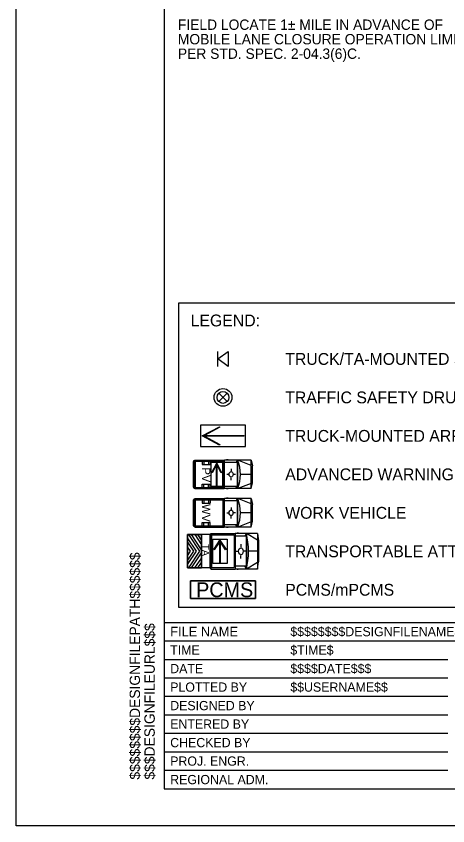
# Model space of a CAD drawing. Extents: x 0 to 17, y 0 to 11.
# Drawn here: x 0 to 2.92, y 0 to 5.47 of the extents above; entities that cross this region are included whole.
import ezdxf

# ---------------------------------------------------------------- set-up
doc = ezdxf.new("R2010")
doc.units = 0
for name, color, linetype in [('SH_GI_PlotLimits', 7, 'Continuous'), ('SH_GI_SheetBorder1', 7, 'Continuous'), ('SH_GI_SheetBorder3', 7, 'Continuous'), ('SH_GI_SheetTextInCells', 7, 'Continuous'), ('SH_GI_TitleBlockText', 7, 'Continuous'), ('TR_SN_SignNotes', 7, 'Continuous'), ('TR_WZ_PCMS', 7, 'Continuous'), ('TR_WZ_PortableChangeMessageSign', 7, 'Continuous'), ('TR_WZ_PortableSignMountBlk-Org', 7, 'Continuous'), ('TR_WZ_ProtectiveVehicle', 7, 'Continuous'), ('TR_WZ_TrafficSafetyDrum', 7, 'Continuous'), ('TR_WZ_TransportableAttenuator', 7, 'Continuous'), ('TR_WZ_WorkZoneTextCurrent', 7, 'Continuous')]:
    doc.layers.add(name, color=color, linetype=linetype)

msp = doc.modelspace()

# ---------------------------------------------------------------- linework, layer by layer
at = {"layer": 'SH_GI_PlotLimits'}
msp.add_lwpolyline([(0, 11), (17, 11), (17, 0), (0, 0)], close=True, dxfattribs=at)
at = {"layer": 'SH_GI_SheetBorder1'}
for p, q in [((1, 1.125), (2.92, 1.125)), ((1, 1), (2.92, 1)), ((1, 0.875), (2.92, 0.875)), ((1, 0.75), (2.92, 0.75)), ((1, 0.625), (2.92, 0.625)), ((1, 0.5), (2.92, 0.5)), ((1, 0.375), (2.92, 0.375))]:
    msp.add_line(p, q, dxfattribs=at)
at = {"layer": 'SH_GI_SheetBorder3'}
for p, q in [((1, 10.75), (1, 0.25)), ((1, 1.375), (16.75, 1.375)), ((1, 1.25), (6.52, 1.25)), ((1, 0.25), (16.75, 0.25))]:
    msp.add_line(p, q, dxfattribs=at)
at = {"layer": 'TR_SN_SignNotes'}
msp.add_ellipse((1.5199, 1.8549), major_axis=(0, 0.0231), ratio=0.642144, dxfattribs=at)
at = {"layer": 'TR_WZ_PCMS'}
for points in [[(1.6191, 1.655), (1.6191, 1.535), (1.1791, 1.535), (1.1791, 1.655), (1.6191, 1.655)], [(1.1791, 1.655), (1.1791, 1.535), (1.6191, 1.535), (1.6191, 1.655), (1.1791, 1.655)]]:
    msp.add_lwpolyline(points, dxfattribs=at)
at = {"layer": 'TR_WZ_PortableSignMountBlk-Org'}
msp.add_line((1.3631, 3.105), (1.3631, 3.205), dxfattribs=at)
msp.add_lwpolyline([(1.3631, 3.155), (1.435, 3.205), (1.435, 3.105)], close=True, dxfattribs=at)
at = {"layer": 'TR_WZ_ProtectiveVehicle'}
for p, q in [((1.2035, 2.4678), (1.2078, 2.4678)), ((1.2078, 2.2822), (1.2078, 2.4678)), ((1.2085, 2.471), (1.406, 2.471)), ((1.2085, 2.279), (1.2085, 2.471)), ((1.2141, 2.2867), (1.2141, 2.4633)), ((1.2141, 2.4633), (1.4004, 2.4633)), ((1.2586, 2.4633), (1.2586, 2.4413)), ((1.2692, 2.4633), (1.2692, 2.4413)), ((1.3018, 2.4633), (1.3018, 2.4413)), ((1.3114, 2.4633), (1.3114, 2.4413)), ((1.4004, 2.2867), (1.4004, 2.4633)), ((1.406, 2.279), (1.406, 2.471)), ((1.4086, 2.279), (1.4086, 2.471)), ((1.59, 2.471), (1.4086, 2.471)), ((1.4334, 2.4737), (1.4225, 2.4737)), ((1.4881, 2.4561), (1.4976, 2.471)), ((1.4976, 2.279), (1.4976, 2.471)), ((1.4993, 2.279), (1.4993, 2.471)), ((1.59, 2.4358), (1.4993, 2.471)), ((1.59, 2.279), (1.59, 2.471)), ((1.59, 2.471), (1.5989, 2.4322)), ((1.1993, 2.288), (1.1993, 2.462)), ((1.2586, 2.4413), (1.3114, 2.4413)), ((1.4976, 2.4561), (1.4086, 2.4561)), ((1.4535, 2.4119), (1.4537, 2.3975)), ((1.5989, 2.3178), (1.5989, 2.4322)), ((1.1993, 2.3885), (1.2078, 2.3849)), ((1.1993, 2.3615), (1.2078, 2.3651)), ((1.2016, 2.375), (1.2055, 2.375)), ((1.2035, 2.3723), (1.2035, 2.3777)), ((1.4245, 2.3757), (1.4388, 2.3754)), ((1.4406, 2.3753), (1.4406, 2.3753)), ((1.4831, 2.3749), (1.471, 2.3749)), ((1.59, 2.375), (1.5171, 2.375)), ((1.2586, 2.3087), (1.3114, 2.3087)), ((1.2586, 2.2867), (1.2586, 2.3087)), ((1.2692, 2.2867), (1.2692, 2.3087)), ((1.3018, 2.2867), (1.3018, 2.3087)), ((1.3114, 2.2867), (1.3114, 2.3087)), ((1.4541, 2.3369), (1.4541, 2.3525)), ((1.59, 2.3142), (1.4993, 2.279)), ((1.59, 2.279), (1.5989, 2.3178)), ((1.2035, 2.2822), (1.2078, 2.2822)), ((1.2085, 2.279), (1.406, 2.279)), ((1.2141, 2.2867), (1.4004, 2.2867)), ((1.4976, 2.2939), (1.4086, 2.2939)), ((1.59, 2.279), (1.4086, 2.279)), ((1.4334, 2.2763), (1.4225, 2.2763)), ((1.4976, 2.279), (1.4861, 2.2939)), ((1.1993, 2.028), (1.1993, 2.202)), ((1.2035, 2.2078), (1.2078, 2.2078)), ((1.2078, 2.0222), (1.2078, 2.2078)), ((1.2085, 2.211), (1.406, 2.211)), ((1.2085, 2.019), (1.2085, 2.211)), ((1.2141, 2.0267), (1.2141, 2.2033)), ((1.2141, 2.2033), (1.4004, 2.2033)), ((1.2586, 2.2033), (1.2586, 2.1813)), ((1.2692, 2.2033), (1.2692, 2.1813)), ((1.3018, 2.2033), (1.3018, 2.1813)), ((1.3114, 2.2033), (1.3114, 2.1813)), ((1.4004, 2.0267), (1.4004, 2.2033)), ((1.406, 2.019), (1.406, 2.211)), ((1.4086, 2.019), (1.4086, 2.211)), ((1.59, 2.211), (1.4086, 2.211)), ((1.4976, 2.1961), (1.4086, 2.1961)), ((1.4334, 2.2137), (1.4225, 2.2137)), ((1.4881, 2.1961), (1.4976, 2.211)), ((1.4976, 2.019), (1.4976, 2.211)), ((1.4993, 2.019), (1.4993, 2.211)), ((1.59, 2.1758), (1.4993, 2.211)), ((1.59, 2.019), (1.59, 2.211)), ((1.59, 2.211), (1.5989, 2.1722)), ((1.2586, 2.1813), (1.3114, 2.1813)), ((1.4535, 2.1519), (1.4537, 2.1375)), ((1.5989, 2.0578), (1.5989, 2.1722)), ((1.1993, 2.1285), (1.2078, 2.1249)), ((1.1993, 2.1015), (1.2078, 2.1051)), ((1.2016, 2.115), (1.2055, 2.115)), ((1.2035, 2.1123), (1.2035, 2.1177)), ((1.4245, 2.1157), (1.4388, 2.1154)), ((1.4406, 2.1153), (1.4406, 2.1153)), ((1.4541, 2.0769), (1.4541, 2.0925)), ((1.4831, 2.1149), (1.471, 2.1149)), ((1.59, 2.115), (1.5171, 2.115)), ((1.2141, 2.0267), (1.4004, 2.0267)), ((1.2586, 2.0487), (1.3114, 2.0487)), ((1.2586, 2.0267), (1.2586, 2.0487)), ((1.2692, 2.0267), (1.2692, 2.0487)), ((1.3018, 2.0267), (1.3018, 2.0487)), ((1.3114, 2.0267), (1.3114, 2.0487)), ((1.4976, 2.0339), (1.4086, 2.0339)), ((1.4976, 2.019), (1.4861, 2.0339)), ((1.59, 2.0542), (1.4993, 2.019)), ((1.59, 2.019), (1.5989, 2.0578)), ((1.2035, 2.0222), (1.2078, 2.0222)), ((1.2085, 2.019), (1.406, 2.019)), ((1.59, 2.019), (1.4086, 2.019)), ((1.4334, 2.0163), (1.4225, 2.0163))]:
    msp.add_line(p, q, dxfattribs=at)
for centre, major_axis, start_param, end_param in [((1.2035, 2.462), (0, 0.00586), 0, 1.570796), ((1.3697, 2.375), (0, 0.2015), 4.215667, 5.208926), ((1.2035, 2.288), (0, -0.00586), 4.712389, 6.283185), ((1.2035, 2.202), (0, 0.00586), 0, 1.570796), ((1.3697, 2.115), (0, 0.2015), 4.215667, 5.208926), ((1.2035, 2.028), (0, -0.00586), 4.712389, 6.283185)]:
    msp.add_ellipse(centre, major_axis=major_axis, ratio=0.73155, start_param=start_param, end_param=end_param, dxfattribs=at)
for centre, major_axis in [((1.2035, 2.375), (0, -0.0027)), ((1.4541, 2.375), (0, -0.0185)), ((1.2035, 2.115), (0, -0.0027)), ((1.4541, 2.115), (0, -0.0185))]:
    msp.add_ellipse(centre, major_axis=major_axis, ratio=0.73155, dxfattribs=at)
at = {"layer": 'TR_WZ_TrafficSafetyDrum'}
for p, q in [((1.3708, 2.9233), (1.4273, 2.8667)), ((1.4273, 2.9233), (1.3708, 2.8667))]:
    msp.add_line(p, q, dxfattribs=at)
for radius in [0.06, 0.06, 0.04]:
    msp.add_circle((1.3991, 2.895), radius, dxfattribs=at)
at = {"layer": 'TR_WZ_TransportableAttenuator'}
for p, q in [((1.3137, 1.971), (1.3173, 1.971)), ((1.3173, 1.971), (1.3173, 1.7389)), ((1.3178, 1.9749), (1.4803, 1.9749)), ((1.3178, 1.9749), (1.3178, 1.735)), ((1.4803, 1.9749), (1.4803, 1.735)), ((1.4825, 1.9749), (1.4825, 1.735)), ((1.6317, 1.9749), (1.4825, 1.9749)), ((1.5038, 1.9784), (1.4949, 1.9784)), ((1.5557, 1.9749), (1.5462, 1.9563)), ((1.5557, 1.9749), (1.5557, 1.735)), ((1.5571, 1.9749), (1.5571, 1.735)), ((1.6317, 1.931), (1.5571, 1.9749)), ((1.6317, 1.9749), (1.6317, 1.735)), ((1.6317, 1.9749), (1.639, 1.9265)), ((1.1591, 1.9172), (1.1591, 1.9464)), ((1.2192, 1.8559), (1.1591, 1.9464)), ((1.1591, 1.9464), (1.1591, 1.9172)), ((1.1591, 1.9172), (1.1999, 1.8562)), ((1.1653, 1.9678), (1.1857, 1.9678)), ((1.1653, 1.9678), (1.2401, 1.8552)), ((1.1857, 1.9678), (1.1653, 1.9678)), ((1.2534, 1.8651), (1.1857, 1.9678)), ((1.2079, 1.9678), (1.2282, 1.9678)), ((1.2282, 1.9678), (1.2079, 1.9678)), ((1.2079, 1.9678), (1.2534, 1.8983)), ((1.2534, 1.9297), (1.2282, 1.9678)), ((1.3178, 1.9678), (1.2534, 1.9678)), ((1.2534, 1.7426), (1.2534, 1.9678)), ((1.2534, 1.9297), (1.2534, 1.8983)), ((1.2534, 1.8983), (1.2534, 1.9297)), ((1.3102, 1.9637), (1.3102, 1.7462)), ((1.3178, 1.9674), (1.3178, 1.7426)), ((1.3224, 1.9654), (1.3224, 1.7446)), ((1.3224, 1.9654), (1.4757, 1.9654)), ((1.4757, 1.9654), (1.4757, 1.7446)), ((1.5557, 1.9563), (1.4825, 1.9563)), ((1.639, 1.9265), (1.639, 1.7834)), ((1.1591, 1.8239), (1.1591, 1.8863)), ((1.18, 1.8553), (1.1591, 1.8863)), ((1.1591, 1.8863), (1.1591, 1.8239)), ((1.2534, 1.8651), (1.2534, 1.845)), ((1.2534, 1.845), (1.2534, 1.8651)), ((1.3102, 1.8718), (1.3173, 1.8674)), ((1.5199, 1.9025), (1.5199, 1.8831)), ((1.1999, 1.8562), (1.1591, 1.7947)), ((1.1591, 1.7653), (1.2192, 1.8559)), ((1.1591, 1.8239), (1.18, 1.8553)), ((1.2401, 1.8552), (1.1653, 1.7424)), ((1.1853, 1.7424), (1.2534, 1.845)), ((1.2534, 1.8119), (1.2073, 1.7424)), ((1.2534, 1.8119), (1.2534, 1.7787)), ((1.2534, 1.7787), (1.2534, 1.8119)), ((1.3102, 1.838), (1.3173, 1.8426)), ((1.3121, 1.855), (1.3154, 1.855)), ((1.3137, 1.8583), (1.3137, 1.8516)), ((1.4882, 1.8551), (1.5015, 1.8551)), ((1.5051, 1.8545), (1.5051, 1.8545)), ((1.5199, 1.8074), (1.5199, 1.8268)), ((1.5517, 1.8551), (1.5384, 1.8551)), ((1.6317, 1.855), (1.5717, 1.855)), ((1.1591, 1.7653), (1.1591, 1.7947)), ((1.1591, 1.7947), (1.1591, 1.7653)), ((1.2289, 1.7424), (1.2534, 1.7787)), ((1.5557, 1.7536), (1.4825, 1.7536)), ((1.5479, 1.7536), (1.5557, 1.735)), ((1.6317, 1.7789), (1.5571, 1.735)), ((1.6317, 1.735), (1.639, 1.7834)), ((1.1853, 1.7424), (1.1653, 1.7424)), ((1.1653, 1.7424), (1.1853, 1.7424)), ((1.2289, 1.7424), (1.2073, 1.7424)), ((1.2073, 1.7424), (1.2289, 1.7424)), ((1.3178, 1.7426), (1.2534, 1.7426)), ((1.3137, 1.7389), (1.3173, 1.7389)), ((1.3178, 1.735), (1.4803, 1.735)), ((1.3224, 1.7446), (1.4757, 1.7446)), ((1.6317, 1.735), (1.4825, 1.735)), ((1.5028, 1.7316), (1.4939, 1.7316))]:
    msp.add_line(p, q, dxfattribs=at)
for points in [[(1.5517, 2.563), (1.5517, 2.707), (1.2464, 2.707), (1.2464, 2.563)], [(1.2587, 2.635), (1.3749, 2.697), (1.3782, 2.693), (1.274, 2.6374)], [(1.2587, 2.635), (1.274, 2.6374), (1.274, 2.6326)], [(1.3749, 2.573), (1.2587, 2.635), (1.274, 2.6326), (1.3782, 2.577)], [(1.5395, 2.6326), (1.274, 2.6326), (1.274, 2.6374), (1.5395, 2.6374)], [(1.3183, 2.4564), (1.3951, 2.4564), (1.3951, 2.2936), (1.3183, 2.2936)], [(1.3236, 2.3879), (1.3567, 2.4499), (1.3554, 2.4417), (1.3257, 2.3861)], [(1.3567, 2.4499), (1.358, 2.4417), (1.3554, 2.4417)], [(1.3554, 2.3001), (1.3554, 2.4417), (1.358, 2.4417), (1.358, 2.3001)], [(1.3567, 2.4499), (1.3897, 2.3879), (1.3876, 2.3861), (1.358, 2.4417)], [(1.2534, 1.7424), (1.1591, 1.7424), (1.1591, 1.9678), (1.2534, 1.9678)], [(1.3304, 1.9364), (1.4264, 1.9364), (1.4264, 1.7735), (1.3304, 1.7735)], [(1.3371, 1.8678), (1.3784, 1.9298), (1.3768, 1.9216), (1.3398, 1.866)], [(1.3784, 1.9298), (1.38, 1.9216), (1.3768, 1.9216)], [(1.3768, 1.7801), (1.3768, 1.9216), (1.38, 1.9216), (1.38, 1.7801)], [(1.3784, 1.9298), (1.4198, 1.8678), (1.4171, 1.866), (1.38, 1.9216)]]:
    msp.add_lwpolyline(points, close=True, dxfattribs=at)
msp.add_lwpolyline([(1.2534, 1.9678), (1.1591, 1.9678), (1.1591, 1.7424), (1.2534, 1.7426)], dxfattribs=at)
for centre, major_axis, start_param, end_param in [((1.3137, 1.9637), (0, 0.00732), 6.283185, 7.853982), ((1.4505, 1.8549), (0, 0.2518), 4.215852, 5.209111), ((1.3137, 1.7462), (0, -0.00732), 4.712389, 6.283185)]:
    msp.add_ellipse(centre, major_axis=major_axis, ratio=0.481608, start_param=start_param, end_param=end_param, dxfattribs=at)
for centre, major_axis, ratio in [((1.5199, 1.8549), (0, -0.0231), 0.642144), ((1.3137, 1.8549), (0, -0.00338), 0.481608)]:
    msp.add_ellipse(centre, major_axis=major_axis, ratio=ratio, dxfattribs=at)
at = {"layer": 'TR_WZ_WorkZoneTextCurrent'}
msp.add_lwpolyline([(1.1, 3.535), (4.2886, 3.535), (4.2886, 1.475), (1.1, 1.475)], close=True, dxfattribs=at)

# ---------------------------------------------------------------- texts
at = {"layer": 'SH_GI_SheetTextInCells'}
for s, height, p in [('FILE NAME', 0.065, (1.042, 1.28)), ('TIME', 0.0625, (1.042, 1.1562)), ('DATE', 0.0625, (1.042, 1.0312)), ('PLOTTED BY', 0.0625, (1.042, 0.9062)), ('DESIGNED BY', 0.0625, (1.042, 0.7812)), ('ENTERED BY', 0.0625, (1.042, 0.6562)), ('CHECKED BY', 0.0625, (1.042, 0.5312)), ('PROJ. ENGR.', 0.0625, (1.042, 0.4062)), ('REGIONAL ADM.', 0.0625, (1.042, 0.2812))]:
    msp.add_text(s, height=height, dxfattribs=at).set_placement(p)
at = {"layer": 'SH_GI_TitleBlockText'}
for s, p in [('$$$$$$$$DESIGNFILEPATH$$$$$$', (0.8377, 0.3125)), ('$$$DESIGNFILEURL$$$', (0.9375, 0.3125))]:
    msp.add_text(s, height=0.07, rotation=90, dxfattribs=at).set_placement(p)
for s, p in [('$$$$$$$$DESIGNFILENAME$$$$$$', (1.8545, 1.2812)), ('$TIME$', (1.8545, 1.1562)), ('$$$$DATE$$$', (1.8545, 1.0312)), ('$$USERNAME$$', (1.8545, 0.9062))]:
    msp.add_text(s, height=0.0625, dxfattribs=at).set_placement(p)
at = {"layer": 'TR_WZ_PCMS'}
msp.add_text('PCMS', height=0.1, rotation=360, dxfattribs=at).set_placement((1.2173, 1.545))
at = {"layer": 'TR_WZ_PortableChangeMessageSign'}
for s, p in [('FIELD LOCATE 1± MILE IN ADVANCE OF ', (1.0938, 5.3789)), ('MOBILE LANE CLOSURE OPERATION LIMITS ', (1.0938, 5.2809)), ('PER STD. SPEC. 2-04.3(6)C.', (1.0938, 5.1829))]:
    msp.add_text(s, height=0.07, rotation=360, dxfattribs=at).set_placement(p)
at = {"layer": 'TR_WZ_ProtectiveVehicle'}
for s, p in [('PV', (1.257, 2.4211)), ('WV', (1.257, 2.1743))]:
    msp.add_text(s, height=0.056, rotation=270, dxfattribs=at).set_placement(p)
at = {"layer": 'TR_WZ_TransportableAttenuator'}
msp.add_text('TA', height=0.048, rotation=270, dxfattribs=at).set_placement((1.2567, 1.9047))
at = {"layer": 'TR_WZ_WorkZoneTextCurrent'}
for s, p in [('LEGEND:', (1.18, 3.375)), ('TRUCK/TA-MOUNTED SIGNS (SEE NOTE 2)', (1.82, 3.115)), ('TRAFFIC SAFETY DRUMS', (1.82, 2.855)), ('TRUCK-MOUNTED ARROW DISPLAY (SEE NOTE 2)', (1.82, 2.595)), ('ADVANCED WARNING VEHICLE', (1.82, 2.335)), ('WORK VEHICLE', (1.82, 2.075)), ('TRANSPORTABLE ATTENUATOR (TL-3)', (1.82, 1.815)), ('PCMS/mPCMS', (1.82, 1.555))]:
    msp.add_text(s, height=0.08, rotation=360, dxfattribs=at).set_placement(p)

doc.saveas('drawing.dxf')
